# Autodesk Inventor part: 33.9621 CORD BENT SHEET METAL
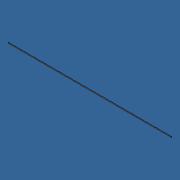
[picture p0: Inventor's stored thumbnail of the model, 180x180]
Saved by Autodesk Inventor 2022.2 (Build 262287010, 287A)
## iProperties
Created: 2018-05
Part Number: 33.9621 CORD BENT SHEET METAL
Material: Generic
Document SubType Name: Sheet Metal
Designer: amoles
Density: 1 g/cm^3
Sheet Metal Rule: Default
Appearance: White
Author: amoles
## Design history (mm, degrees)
node "Face1"
  sketch "Sketch1"
    geometry: L1 (-787.4, 3.5)-(787.4, 3.5); L2 (787.4, 3.5)-(787.4, -3.5); L3 (787.4, -3.5)-(-787.4, -3.5); L4 (-787.4, -3.5)-(-787.4, 3.5); 3 further points
    constraints: 8 end point, 2 midpoint, 2 parallel, 1 horizontal, 1 horizontal alignment, 1 perpendicular, 1 vertical alignment
    dimensions: "d0" = 7 distance of L3.end L1.start; "d1" = 1574.8 distance of L1.start L1.end
body "Solid1"
face "Plate1" dims "d2" = 3.3 (= Thickness)
other parameters: "Thickness" = 3.3 (derived), "BendRadius" = 26.4 (= 8 x Thickness), "BendReliefWidth" = 3.3 (= Thickness), "BendReliefDepth" = 1.65 (= 0.5 x Thickness), "CornerReliefSize" = 13.2 (= 4 x Thickness), "SeamGap" = 0.00508, "MinimumRemnant" = 6.6 (= 2 x Thickness), "TransitionRadius" = 26.4 (= BendRadius), "JacobiRadiusSize" = 26.4 (= BendRadius), "GapSize" = 3.3 (= Thickness)
